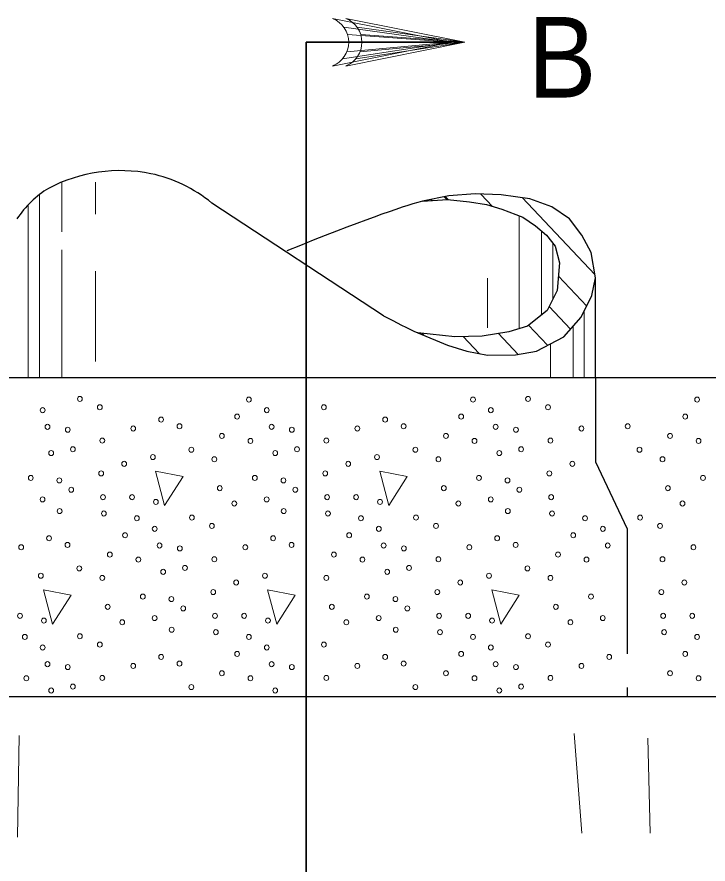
# Model space of a CAD drawing. Extents: x -410.5 to -376.5, y 1617.6 to 1661.6.
# Drawn here: x -403.909 to -401.85, y 1646.914 to 1649.436 of the extents above; entities that cross this region are included whole.
import ezdxf

# ---------------------------------------------------------------- set-up
doc = ezdxf.new("R2010")
doc.units = 0
doc.header["$LTSCALE"] = 0.062
doc.linetypes.add('LONG_DASHED', pattern=[7.5, 6, -1.5])
doc.layers.add('1', color=7, linetype='Continuous', lineweight=13)

msp = doc.modelspace()

# ---------------------------------------------------------------- linework, layer by layer
at = {"layer": '1'}
for p, q in [((-402.93492, 1649.40567), (-402.61442, 1649.36083)), ((-402.89558, 1649.40567), (-402.57508, 1649.36083)), ((-402.92408, 1649.3835), (-402.61442, 1649.36083)), ((-402.88475, 1649.3835), (-402.57508, 1649.36083)), ((-402.93875, 1649.31133), (-402.61442, 1649.36083)), ((-402.92642, 1649.33208), (-402.61442, 1649.36083)), ((-402.92075, 1649.36083), (-402.61442, 1649.36083)), ((-402.89942, 1649.31133), (-402.57508, 1649.36083)), ((-402.88708, 1649.33208), (-402.57508, 1649.36083)), ((-402.88142, 1649.36083), (-402.57508, 1649.36083)), ((-403.77533, 1648.79592), (-403.77533, 1648.94417)), ((-403.67517, 1648.84867), (-403.67517, 1648.94417)), ((-403.84208, 1648.3615), (-403.84208, 1648.90692)), ((-402.62792, 1648.89233), (-402.63625, 1648.90092)), ((-402.62442, 1648.89225), (-402.63333, 1648.90158)), ((-402.49208, 1648.87175), (-402.527, 1648.90892)), ((-403.8755, 1648.3615), (-403.8755, 1648.87675)), ((-402.6725, 1648.88958), (-402.67575, 1648.893)), ((-402.18725, 1648.66892), (-402.4035, 1648.89808)), ((-402.41267, 1648.50817), (-402.41267, 1648.84417)), ((-402.34592, 1648.54892), (-402.34592, 1648.79842)), ((-402.3125, 1648.59517), (-402.3125, 1648.76183)), ((-403.77533, 1648.3615), (-403.77533, 1648.74317)), ((-403.67517, 1648.40983), (-403.67517, 1648.67908)), ((-402.50725, 1648.51033), (-402.50725, 1648.65842)), ((-402.21167, 1648.57508), (-402.29592, 1648.66425)), ((-402.25983, 1648.50608), (-402.32358, 1648.57358)), ((-402.21875, 1648.3615), (-402.21875, 1648.56067)), ((-402.32825, 1648.45858), (-402.3845, 1648.51817)), ((-402.25208, 1648.3615), (-402.25208, 1648.51467)), ((-402.70983, 1648.4935), (-402.71125, 1648.49525)), ((-402.69567, 1648.48775), (-402.70183, 1648.49417)), ((-402.53167, 1648.43417), (-402.57917, 1648.48433)), ((-402.41567, 1648.43125), (-402.47467, 1648.49367)), ((-402.31892, 1648.3615), (-402.31892, 1648.4635)), ((-403.90242, 1647.29658), (-403.90733, 1646.99375)), ((-402.24892, 1647.30308), (-402.22642, 1647.00633)), ((-402.02992, 1647.28875), (-402.02208, 1647.00575))]:
    msp.add_line(p, q, dxfattribs=at)
at = {"layer": '1', "lineweight": 35}
for q in [(-402.61442, 1649.36083), (-403.04708, 1646.83792)]:
    msp.add_line((-403.04708, 1649.36083), q, dxfattribs=at)
at = {"layer": '1', "lineweight": 25}
for p, q in [((-402.81658, 1648.54667), (-403.32842, 1648.88217)), ((-402.18542, 1648.3615), (-402.18542, 1648.65917))]:
    msp.add_line(p, q, dxfattribs=at)
at = {"layer": '1'}
for points in [[(-402.96842, 1649.29008), (-402.61442, 1649.36083), (-402.96842, 1649.43167)], [(-402.92908, 1649.29008), (-402.57508, 1649.36083), (-402.92908, 1649.43167)]]:
    msp.add_lwpolyline(points, dxfattribs=at)
at = {"layer": '1', "lineweight": 25}
for points in [[(-402.71458, 1648.49558), (-402.62625, 1648.45908), (-402.56858, 1648.44092), (-402.50683, 1648.42942), (-402.42408, 1648.42975), (-402.36108, 1648.4415), (-402.27925, 1648.484), (-402.22817, 1648.54192), (-402.196, 1648.60658), (-402.18542, 1648.65917), (-402.19833, 1648.73458), (-402.22558, 1648.7865), (-402.26292, 1648.83458), (-402.31508, 1648.871), (-402.38108, 1648.895), (-402.46667, 1648.90692), (-402.54342, 1648.90942), (-402.622, 1648.90392), (-402.70117, 1648.88783)], [(-402.71458, 1648.49558), (-402.62625, 1648.45908), (-402.56858, 1648.44092), (-402.50683, 1648.42942), (-402.42408, 1648.42975), (-402.36108, 1648.4415), (-402.27925, 1648.484), (-402.22817, 1648.54192), (-402.196, 1648.60658), (-402.18542, 1648.65917), (-402.19833, 1648.73458), (-402.22558, 1648.7865), (-402.26292, 1648.83458), (-402.31508, 1648.871), (-402.38108, 1648.895), (-402.46667, 1648.90692), (-402.54342, 1648.90942), (-402.622, 1648.90392), (-402.70117, 1648.88783)], [(-402.70117, 1648.88783), (-402.62658, 1648.8925), (-402.56033, 1648.8855), (-402.50975, 1648.87725), (-402.46417, 1648.86342), (-402.40192, 1648.84008), (-402.36425, 1648.81392), (-402.33175, 1648.7865), (-402.30583, 1648.7535), (-402.29275, 1648.704), (-402.29925, 1648.6215), (-402.32917, 1648.56217), (-402.38758, 1648.51558), (-402.44342, 1648.499), (-402.52275, 1648.48525), (-402.6045, 1648.48392), (-402.71458, 1648.49558)], [(-402.70117, 1648.88783), (-402.62658, 1648.8925), (-402.56033, 1648.8855), (-402.50975, 1648.87725), (-402.46417, 1648.86342), (-402.40192, 1648.84008), (-402.36425, 1648.81392), (-402.33175, 1648.7865), (-402.30583, 1648.7535), (-402.29275, 1648.704), (-402.29925, 1648.6215), (-402.32917, 1648.56217), (-402.38758, 1648.51558), (-402.44342, 1648.499), (-402.52275, 1648.48525), (-402.6045, 1648.48392), (-402.71458, 1648.49558)], [(-404.46308, 1644.36383), (-404.46308, 1644.36375), (-401.63108, 1644.36375), (-401.63108, 1647.41208), (-404.46308, 1647.41208)]]:
    msp.add_lwpolyline(points, dxfattribs=at)
msp.add_lwpolyline([(-405.35992, 1643.41425), (-400.73433, 1643.41425), (-400.73433, 1648.3615), (-405.35992, 1648.3615), (-405.35992, 1647.537), (-405.35992, 1644.23892)], close=True, dxfattribs=at)
at = {"layer": '1', "linetype": 'LONG_DASHED', "lineweight": 25}
msp.add_lwpolyline([(-402.18542, 1648.3615), (-402.18542, 1648.11167), (-402.091, 1647.91175), (-402.091, 1647.41208)], dxfattribs=at)
at = {"layer": '1'}
for points in [[(-403.49575, 1648.08408), (-403.46875, 1647.98167), (-403.41375, 1648.06817)], [(-402.82825, 1648.08408), (-402.80125, 1647.98167), (-402.74633, 1648.06817)], [(-403.82942, 1647.73075), (-403.80258, 1647.62833), (-403.74758, 1647.71483)], [(-403.162, 1647.73075), (-403.135, 1647.62833), (-403.08008, 1647.71483)], [(-402.4945, 1647.73075), (-402.4675, 1647.62833), (-402.4125, 1647.71483)]]:
    msp.add_lwpolyline(points, close=True, dxfattribs=at)
for centre in [(-402.99704, 1649.36094), (-402.9577, 1649.36094)]:
    msp.add_arc(centre, 0.0764, 292.08605, 67.91218, dxfattribs=at)
at = {"layer": '1', "lineweight": 25}
for centre, major_axis, start_param, end_param in [((-403.60136, 1648.46974), (0, -0.5089), 2.9497702, 3.6011474), ((-403.59386, 1648.51828), (0, 0.45979), 5.6254463, 6.0881824), ((-403.67086, 1648.65916), (0, 0.30703), 0.5184487, 0.9622613)]:
    msp.add_ellipse(centre, major_axis=major_axis, ratio=0.944543, start_param=start_param, end_param=end_param, dxfattribs=at)
at = {"layer": '1'}
for centre, major_axis in [((-403.7213, 1648.29871), (0, -0.00756)), ((-403.21777, 1648.29682), (0, 0.00756)), ((-402.55026, 1648.29682), (0, 0.00756)), ((-402.38628, 1648.29871), (0, -0.00756)), ((-401.88276, 1648.29682), (0, 0.00756)), ((-403.83216, 1648.26531), (0, 0.00756)), ((-403.66183, 1648.27391), (0, -0.00756)), ((-403.16465, 1648.26531), (0, 0.00756)), ((-402.99432, 1648.27391), (0, -0.00756)), ((-402.49714, 1648.26531), (0, 0.00756)), ((-402.32682, 1648.27391), (0, -0.00756)), ((-403.47944, 1648.23734), (0, -0.00756)), ((-403.25298, 1648.24623), (0, 0.00756)), ((-402.81193, 1648.23734), (0, -0.00756)), ((-402.58548, 1648.24623), (0, 0.00756)), ((-401.91797, 1648.24623), (0, 0.00756)), ((-403.8177, 1648.21573), (0, 0.00756)), ((-403.56237, 1648.21066), (0, -0.00756)), ((-403.42448, 1648.21732), (0, -0.00756)), ((-403.15019, 1648.21573), (0, 0.00756)), ((-402.89487, 1648.21066), (0, -0.00756)), ((-402.75697, 1648.21732), (0, -0.00756)), ((-402.48268, 1648.21573), (0, 0.00756)), ((-402.22736, 1648.21066), (0, -0.00756)), ((-402.08946, 1648.21732), (0, -0.00756)), ((-403.75734, 1648.20707), (0, -0.00756)), ((-403.29832, 1648.1887), (0, 0.00756)), ((-403.08983, 1648.20707), (0, -0.00756)), ((-402.63081, 1648.1887), (0, 0.00756)), ((-402.42233, 1648.20707), (0, -0.00756)), ((-401.9633, 1648.1887), (0, 0.00756)), ((-403.6546, 1648.17462), (0, -0.00756)), ((-403.21332, 1648.17374), (0, 0.00756)), ((-402.98709, 1648.17462), (0, -0.00756)), ((-402.54581, 1648.17374), (0, 0.00756)), ((-402.31958, 1648.17462), (0, -0.00756)), ((-401.87831, 1648.17374), (0, 0.00756)), ((-403.80696, 1648.13746), (0, -0.00756)), ((-403.74205, 1648.14894), (0, -0.00756)), ((-403.38938, 1648.14765), (0, 0.00756)), ((-403.13945, 1648.13746), (0, -0.00756)), ((-403.07454, 1648.14894), (0, -0.00756)), ((-402.72187, 1648.14765), (0, 0.00756)), ((-402.47194, 1648.13746), (0, -0.00756)), ((-402.40703, 1648.14894), (0, -0.00756)), ((-402.05436, 1648.14765), (0, 0.00756)), ((-403.5038, 1648.12568), (0, -0.00756)), ((-403.32085, 1648.11903), (0, 0.00756)), ((-402.83629, 1648.12568), (0, -0.00756)), ((-402.65334, 1648.11903), (0, 0.00756)), ((-401.98583, 1648.11903), (0, 0.00756)), ((-403.58946, 1648.10566), (0, -0.00756)), ((-402.92196, 1648.10566), (0, -0.00756)), ((-402.25445, 1648.10566), (0, -0.00756)), ((-403.86759, 1648.06373), (0, -0.00756)), ((-403.65788, 1648.07704), (0, -0.00756)), ((-403.20008, 1648.06373), (0, -0.00756)), ((-402.99038, 1648.07704), (0, -0.00756)), ((-402.53258, 1648.06373), (0, -0.00756)), ((-402.32287, 1648.07704), (0, -0.00756)), ((-401.86507, 1648.06373), (0, -0.00756)), ((-403.78254, 1648.05637), (0, -0.00756)), ((-403.11503, 1648.05637), (0, -0.00756)), ((-402.44752, 1648.05637), (0, -0.00756)), ((-403.74711, 1648.02839), (0, -0.00756)), ((-403.3046, 1648.03316), (0, -0.00756)), ((-403.0796, 1648.02839), (0, -0.00756)), ((-402.6371, 1648.03316), (0, -0.00756)), ((-402.41209, 1648.02839), (0, -0.00756)), ((-401.96959, 1648.03316), (0, -0.00756)), ((-403.83244, 1647.99977), (0, -0.00756)), ((-403.65249, 1648.00643), (0, -0.00756)), ((-403.56593, 1648.00643), (0, 0.00756)), ((-403.49479, 1647.99212), (0, -0.00756)), ((-403.26133, 1647.98735), (0, -0.00756)), ((-403.16493, 1647.99977), (0, -0.00756)), ((-402.98498, 1648.00643), (0, -0.00756)), ((-402.89843, 1648.00643), (0, 0.00756)), ((-402.82728, 1647.99212), (0, -0.00756)), ((-402.59382, 1647.98735), (0, -0.00756)), ((-402.49742, 1647.99977), (0, -0.00756)), ((-402.31747, 1648.00643), (0, -0.00756)), ((-401.92631, 1647.98735), (0, -0.00756)), ((-403.78165, 1647.96509), (0, -0.00756)), ((-403.11414, 1647.96509), (0, -0.00756)), ((-402.44663, 1647.96509), (0, -0.00756)), ((-403.64982, 1647.95778), (0, -0.00756)), ((-403.55153, 1647.94347), (0, 0.00756)), ((-403.38754, 1647.94536), (0, -0.00756)), ((-402.98231, 1647.95778), (0, -0.00756)), ((-402.88402, 1647.94347), (0, 0.00756)), ((-402.72003, 1647.94536), (0, -0.00756)), ((-402.3148, 1647.95778), (0, -0.00756)), ((-402.21651, 1647.94347), (0, 0.00756)), ((-402.05253, 1647.94536), (0, -0.00756)), ((-403.4984, 1647.91196), (0, 0.00756)), ((-403.32808, 1647.92056), (0, -0.00756)), ((-402.8309, 1647.91196), (0, 0.00756)), ((-402.66057, 1647.92056), (0, -0.00756)), ((-402.16339, 1647.91196), (0, 0.00756)), ((-401.99306, 1647.92056), (0, -0.00756)), ((-403.81319, 1647.88399), (0, -0.00756)), ((-403.58674, 1647.89288), (0, 0.00756)), ((-403.14568, 1647.88399), (0, -0.00756)), ((-402.91923, 1647.89288), (0, 0.00756)), ((-402.47817, 1647.88399), (0, -0.00756)), ((-402.25172, 1647.89288), (0, 0.00756)), ((-403.89613, 1647.85731), (0, -0.00756)), ((-403.75823, 1647.86397), (0, -0.00756)), ((-403.48394, 1647.86238), (0, 0.00756)), ((-403.22862, 1647.85731), (0, -0.00756)), ((-403.09072, 1647.86397), (0, -0.00756)), ((-402.81643, 1647.86238), (0, 0.00756)), ((-402.56111, 1647.85731), (0, -0.00756)), ((-402.42322, 1647.86397), (0, -0.00756)), ((-402.14893, 1647.86238), (0, 0.00756)), ((-401.8936, 1647.85731), (0, -0.00756)), ((-403.63207, 1647.83535), (0, 0.00756)), ((-403.42359, 1647.85372), (0, -0.00756)), ((-402.96456, 1647.83535), (0, 0.00756)), ((-402.75608, 1647.85372), (0, -0.00756)), ((-402.29706, 1647.83535), (0, 0.00756)), ((-403.54708, 1647.82039), (0, 0.00756)), ((-403.32085, 1647.82127), (0, -0.00756)), ((-402.87957, 1647.82039), (0, 0.00756)), ((-402.65334, 1647.82127), (0, -0.00756)), ((-402.21206, 1647.82039), (0, 0.00756)), ((-401.98583, 1647.82127), (0, -0.00756)), ((-403.72313, 1647.7943), (0, 0.00756)), ((-403.47321, 1647.78411), (0, -0.00756)), ((-403.40829, 1647.79559), (0, -0.00756)), ((-402.8057, 1647.78411), (0, -0.00756)), ((-402.74078, 1647.79559), (0, -0.00756)), ((-402.38812, 1647.7943), (0, 0.00756)), ((-403.83755, 1647.77233), (0, -0.00756)), ((-403.6546, 1647.76568), (0, 0.00756)), ((-403.17005, 1647.77233), (0, -0.00756)), ((-402.98709, 1647.76568), (0, 0.00756)), ((-402.50254, 1647.77233), (0, -0.00756)), ((-402.31958, 1647.76568), (0, 0.00756)), ((-403.25571, 1647.75231), (0, -0.00756)), ((-402.5882, 1647.75231), (0, -0.00756)), ((-401.92069, 1647.75231), (0, -0.00756)), ((-403.53384, 1647.71038), (0, -0.00756)), ((-403.32413, 1647.72369), (0, -0.00756)), ((-402.86633, 1647.71038), (0, -0.00756)), ((-402.65662, 1647.72369), (0, -0.00756)), ((-402.19882, 1647.71038), (0, -0.00756)), ((-401.98911, 1647.72369), (0, -0.00756)), ((-403.44879, 1647.70302), (0, -0.00756)), ((-402.78128, 1647.70302), (0, -0.00756)), ((-403.63836, 1647.67981), (0, -0.00756)), ((-403.41335, 1647.67504), (0, -0.00756)), ((-402.97085, 1647.67981), (0, -0.00756)), ((-402.74584, 1647.67504), (0, -0.00756)), ((-402.30334, 1647.67981), (0, -0.00756)), ((-403.89969, 1647.65308), (0, 0.00756)), ((-403.82854, 1647.63877), (0, -0.00756)), ((-403.59508, 1647.634), (0, -0.00756)), ((-403.49868, 1647.64642), (0, -0.00756)), ((-403.31873, 1647.65308), (0, -0.00756)), ((-403.23218, 1647.65308), (0, 0.00756)), ((-403.16103, 1647.63877), (0, -0.00756)), ((-402.92757, 1647.634), (0, -0.00756)), ((-402.83117, 1647.64642), (0, -0.00756)), ((-402.65123, 1647.65308), (0, -0.00756)), ((-402.56467, 1647.65308), (0, 0.00756)), ((-402.49353, 1647.63877), (0, -0.00756)), ((-402.26007, 1647.634), (0, -0.00756)), ((-402.16367, 1647.64642), (0, -0.00756)), ((-401.98372, 1647.65308), (0, -0.00756)), ((-401.89716, 1647.65308), (0, 0.00756)), ((-403.4479, 1647.61174), (0, -0.00756)), ((-402.78039, 1647.61174), (0, -0.00756)), ((-403.88528, 1647.59012), (0, 0.00756)), ((-403.7213, 1647.59201), (0, -0.00756)), ((-403.31606, 1647.60443), (0, -0.00756)), ((-403.21777, 1647.59012), (0, 0.00756)), ((-402.64856, 1647.60443), (0, -0.00756)), ((-402.55026, 1647.59012), (0, 0.00756)), ((-402.38628, 1647.59201), (0, -0.00756)), ((-401.98105, 1647.60443), (0, -0.00756)), ((-401.88276, 1647.59012), (0, 0.00756)), ((-403.83216, 1647.55861), (0, 0.00756)), ((-403.66183, 1647.56721), (0, -0.00756)), ((-403.16465, 1647.55861), (0, 0.00756)), ((-402.99432, 1647.56721), (0, -0.00756)), ((-402.49714, 1647.55861), (0, 0.00756)), ((-402.32682, 1647.56721), (0, -0.00756)), ((-403.47944, 1647.53064), (0, -0.00756)), ((-403.25298, 1647.53953), (0, 0.00756)), ((-402.81193, 1647.53064), (0, -0.00756)), ((-402.58548, 1647.53953), (0, 0.00756)), ((-402.14442, 1647.53064), (0, -0.00756)), ((-401.91797, 1647.53953), (0, 0.00756)), ((-403.8177, 1647.50903), (0, 0.00756)), ((-403.42448, 1647.51062), (0, -0.00756)), ((-403.15019, 1647.50903), (0, 0.00756)), ((-402.75697, 1647.51062), (0, -0.00756)), ((-402.48268, 1647.50903), (0, 0.00756)), ((-403.75734, 1647.50037), (0, -0.00756)), ((-403.56237, 1647.50396), (0, -0.00756)), ((-403.29832, 1647.482), (0, 0.00756)), ((-403.08983, 1647.50037), (0, -0.00756)), ((-402.89487, 1647.50396), (0, -0.00756)), ((-402.63081, 1647.482), (0, 0.00756)), ((-402.42233, 1647.50037), (0, -0.00756)), ((-402.22736, 1647.50396), (0, -0.00756)), ((-401.9633, 1647.482), (0, 0.00756)), ((-403.88083, 1647.46704), (0, 0.00756)), ((-403.6546, 1647.46792), (0, -0.00756)), ((-403.21332, 1647.46704), (0, 0.00756)), ((-402.98709, 1647.46792), (0, -0.00756)), ((-402.54581, 1647.46704), (0, 0.00756)), ((-402.31958, 1647.46792), (0, -0.00756)), ((-401.87831, 1647.46704), (0, 0.00756)), ((-403.80696, 1647.43076), (0, -0.00756)), ((-403.74205, 1647.44225), (0, -0.00756)), ((-403.38938, 1647.44095), (0, 0.00756)), ((-403.13945, 1647.43076), (0, -0.00756)), ((-402.72187, 1647.44095), (0, 0.00756)), ((-402.47194, 1647.43076), (0, -0.00756)), ((-402.40703, 1647.44225), (0, -0.00756))]:
    msp.add_ellipse(centre, major_axis=major_axis, ratio=0.944543, dxfattribs=at)
at = {"layer": '1', "lineweight": 25}
for points in [[(-402.70117, 1648.88783), (-402.77, 1648.869), (-402.88042, 1648.82933), (-403.10508, 1648.73983)], [(-402.81658, 1648.54667), (-402.779, 1648.5265), (-402.745, 1648.50967), (-402.71458, 1648.49558)]]:
    msp.add_open_spline(points, degree=3, dxfattribs=at)

# ---------------------------------------------------------------- texts
at = {"layer": '1', "width": 0.95}
msp.add_text('B', height=0.24, dxfattribs=at).set_placement((-402.38633, 1649.19617))

doc.saveas('drawing.dxf')
